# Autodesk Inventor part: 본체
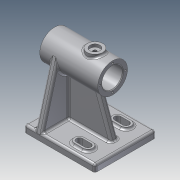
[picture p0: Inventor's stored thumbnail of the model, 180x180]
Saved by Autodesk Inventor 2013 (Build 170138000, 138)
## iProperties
Created: 2019-10
Part Number: 본체
Material: 알루미늄 6061
Document SubType Name: Modeling
Designer: a
Mass: 588.617 g
Surface Area: 540.349 cm^2
Volume: 217.202 cm^3
Density: 2.71 g/cm^3
Author: a
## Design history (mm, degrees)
sketch "스케치1"
  geometry: C1 r 21 at (0, 0); 1 further point
  constraints: 1 centre point, 1 coincident
  dimensions: "d0" = 42 diameter of C1
extrude "돌출1" new body sketch "스케치1" distance "d1" = 82; taper "d2" = 0 deg
sketch "스케치2"
  geometry: C1 r 21 at (0, 0) reference; 1 further point
  constraints: 1 coincident
hole "구멍1" sketch "스케치2" at (0, 0) diameter "d3" = 23; stored, may be unused: countersink angle "d7" = 90 deg, drill point angle "d9" = 118 deg; dims "d4" = 6, "d5" = 29, "d6" = 62, "d8" = 8
sketch "스케치3"
  geometry: L1 (0, 0)-(0, 18); C1 r 21 at (0, 0) reference; 1 further point
  constraints: 2 end point, 1 coincident, 1 vertical
  dimensions: "d10" = 18 distance of L1.start L1.end
hole "구멍2" sketch "스케치3" at (0, 18) diameter "d11" = 2.459; stored, may be unused: countersink angle "d15" = 90 deg, drill point angle "d17" = 118 deg; dims "d12" = 8, "d13" = 29, "d14" = 62, "d16" = 10
sketch "스케치4"
  geometry: L1 (0, 0)-(0, 18); C1 r 21 at (0, 0) reference; 1 further point
  constraints: 2 end point, 1 coincident, 1 vertical
  dimensions: "d21" = 18 distance of L1.start L1.end
hole "구멍3" sketch "스케치4" at (0, 18) diameter "d22" = 2.459; stored, may be unused: countersink angle "d26" = 90 deg, drill point angle "d28" = 118 deg; dims "d23" = 8, "d24" = 29, "d25" = 62, "d27" = 10
node "작업 평면1"
sketch "스케치5"
  geometry: L1 (43, 100)-(-43, 100); L2 (-43, 100)-(-43, 0); L3 (-43, 0)-(43, 0); L4 (43, 0)-(43, 100); 2 further points
  constraints: 8 end point, 2 parallel, 1 coincident, 1 horizontal, 1 midpoint, 1 perpendicular
  dimensions: "d33" = 86 distance of L3.end L2.end; "d34" = 100 distance of L2.end L1.end
extrude "돌출2" join sketch "스케치5" distance "d35" = 10; taper "d36" = 0 deg
fillet "모깎기3" dims "d64" = 3
fillet "모깎기4" dims "d65" = 3
sketch "스케치6"
  geometry: L1 (-43, -100)-(43, -100) reference; L2 (-43, 0)-(-43, -100) reference; L3 (0, -100)-(0, -85); L4 (-5, -85)-(5, -85); L5 (5, -85)-(5, -15); L6 (5, -15)-(-5, -15); L7 (-5, -15)-(-5, -85); 1 further point
  constraints: 10 end point, 3 parallel, 2 midpoint, 1 horizontal, 1 perpendicular
  dimensions: "d37" = 15 distance of L3.end L3.start; "d38" = 10 distance of L6.end L5.end; "d39" = 70 distance of L5.end L4.end
extrude "돌출3" join sketch "스케치6" distance "d40" = 60; taper "d41" = 0 deg
feature "면 기울기1" dims angle "d42" = 20 deg
node "작업 평면2"
sketch "스케치8"
  geometry: L1 (-43, -100)-(43, -100) reference; L2 (-34, -62)-(-20, -62); L3 (-20, -62)-(-20, -74); L4 (-20, -74)-(-34, -74); L5 (-34, -74)-(-34, -62); A1 r 7 centre (-27, -62) between (-20, -62) and (-34, -62); A2 r 7 centre (-27, -74) between (-34, -74) and (-20, -74); 1 further point
  constraints: 8 end point, 4 point on circle, 2 centre point, 2 midpoint, 2 parallel, 1 horizontal, 1 perpendicular
  dimensions: "d50" = 14 distance of L3.end L4.end; "d51" = 12 distance of L3.end L2.end; "d52" = 27 horizontal distance of A1.centre point (0, 0); "d53" = 26 distance from line of L1 A2.centre
extrude "돌출4" join sketch "스케치8" distance "d54" = 3; taper "d55" = 0 deg
sketch "스케치9"
  geometry: L1 (-31.5, -62)-(-22.5, -62); L2 (-22.5, -62)-(-22.5, -74); L3 (-22.5, -74)-(-31.5, -74); L4 (-31.5, -74)-(-31.5, -62); C1 r 4.5 at (-27, -62); C2 r 4.5 at (-27, -74); A1 r 7 centre (-27, -62) between (-20, -62) and (-34, -62) reference; A2 r 7 centre (-27, -74) between (-34, -74) and (-20, -74) reference; 2 further points
  constraints: 8 end point, 3 coincident, 2 centre point, 2 parallel, 1 horizontal, 1 midpoint, 1 perpendicular
  dimensions: "d56" = 9 diameter of C1; "d57" = 9 diameter of C2; "d58" = 9 distance of L2.end L3.end; "d59" = 12 distance of L1.end L2.end
extrude "돌출5" cut sketch "스케치9" stored distance "d60" = 3; taper "d61" = 0 deg
node "작업 평면3"
sketch "스케치10"
  geometry: L1 (43, -79)-(43, -86) reference; L2 (43, -86)-(-43, -86) reference; L3 (-43, -86)-(-43, -79) reference; L4 (-40, -76)-(-5, -76) reference; L5 (-5, -76)-(-5, -20.396) reference; L6 (5, -20.396)-(5, -76) reference; L7 (5, -76)-(40, -76) reference; L8 (42.896, -78.217)-(20.272, 5.48); C1 r 14.5 at (0, 0) reference; C2 r 11.5 at (0, 0) reference; A1 r 3 centre (40, -79) between (43, -79) and (40, -76) reference; A2 r 3 centre (-40, -79) between (-40, -76) and (-43, -79) reference; A3 r 21 centre (0, 0) between (5, -20.396) and (-5, -20.396) reference; 1 further point
  constraints: 2 end point, 2 point on circle, 2 tangent
feature "리브2" sketch "스케치10" dims "d67" = 1, "d68" = 10, "d69" = 0, "d70" = 0, "d71" = 1, "d72" = 1
fillet "모깎기5" dims "d73" = 3
fillet "모깎기6" dims "d74" = 3
fillet "모깎기7" dims "d75" = 3
node "작업 평면4"
sketch "스케치11"
  geometry: L1 (21, 82)-(-21, 82) reference; L2 (0, 82)-(0, 57); C1 r 11 at (0, 57); 1 further point
  constraints: 2 end point, 1 centre point, 1 coincident, 1 midpoint, 1 perpendicular
  dimensions: "d77" = 25 distance of L2.start L2.end; "d78" = 22 diameter of C1
extrude "돌출6" join sketch "스케치11" stored distance "d79" = 60; taper "d80" = 0 deg
sketch "스케치12"
  geometry: C1 r 11 at (0, 0) reference; 2 further points
  constraints: 1 coincident
hole "구멍4" sketch "스케치12" at (0, 0) diameter "d81" = 4.917; stored, may be unused: countersink angle "d85" = 90 deg, drill point angle "d87" = 118 deg; dims "d82" = 8, "d83" = 14, "d84" = 4, "d86" = 10
fillet "모깎기8" dims "d91" = 3
chamfer "모따기1" distance "d92" = 1; stored, may be unused: second distance "d93" = 2, angle "d94" = 45 deg
sketch "스케치13"
  geometry: L1 (43, -97)-(43, -3) reference; 2 further points
  constraints: 1 other
  dimensions: "d95" = 7 distance of point (0, 0) point (0, -7); "d96" = 43 distance from line of point (0, -7) L1
feature "엠보싱1" sketch "스케치13" dims "d23" = 8, "d97" = 0.5, "d98" = 0
node "솔리드1"
pattern_circular "원형 패턴2" dims angle "d30" = 360 deg
mirror "대칭2"
mirror "대칭3"
pattern_circular "원형 패턴3" dims angle "d89" = 360 deg
node "절단 모서리 투영2"
other parameters: "d32" = -86, "d76" = 24
